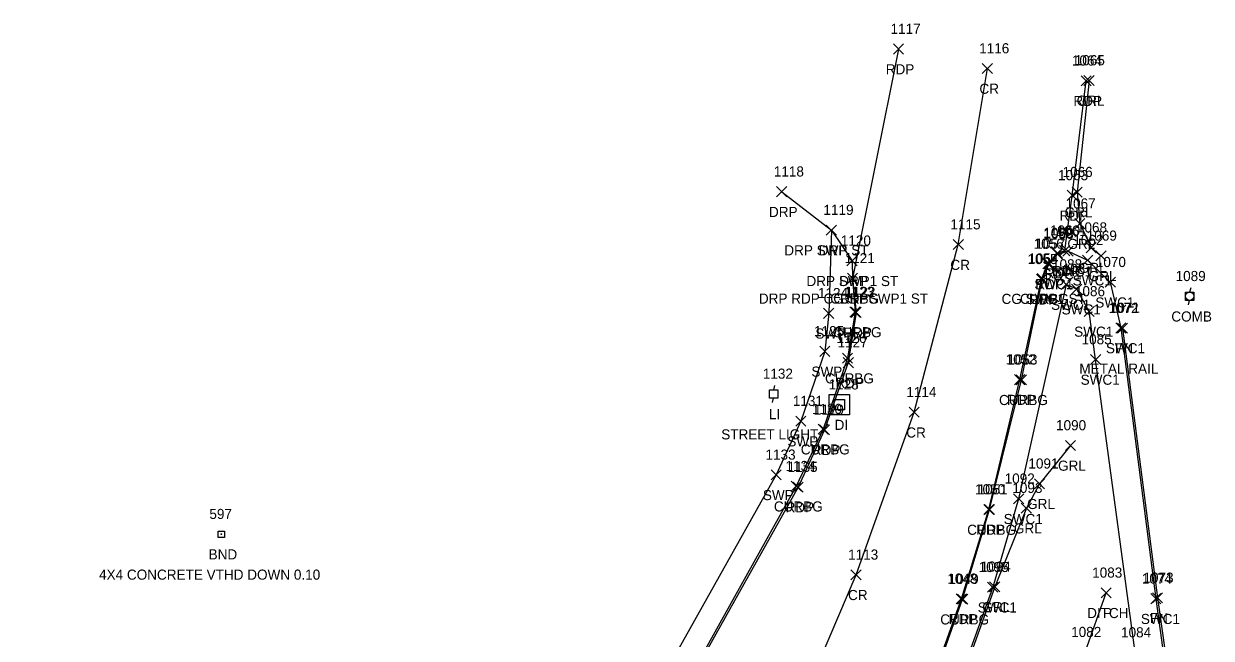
# Model space of a CAD drawing. Extents: x 1690689 to 1696275, y 438760 to 444007.
# Drawn here: x 1692953 to 1693187.6, y 438961.2 to 439082.7 of the extents above; entities that cross this region are included whole.
import ezdxf

# ---------------------------------------------------------------- set-up
doc = ezdxf.new("R2010")
doc.units = 0
for name, color, linetype in [('D_A', 7, 'Continuous'), ('D_I', 7, 'Continuous'), ('D_TIC', 7, 'Continuous'), ('DD', 7, 'Continuous'), ('DS', 7, 'Continuous'), ('L_A', 7, 'Continuous'), ('L_C', 7, 'Continuous'), ('L_I', 7, 'Continuous'), ('L_TIC', 7, 'Continuous'), ('Level 18', 7, 'Continuous'), ('LFNC', 7, 'Continuous'), ('M_A', 7, 'Continuous'), ('M_C', 7, 'Continuous'), ('M_I', 7, 'Continuous'), ('P_A', 7, 'Continuous'), ('P_I', 7, 'Continuous'), ('P_TIC', 7, 'Continuous'), ('PET', 7, 'Continuous'), ('PRC', 7, 'Continuous'), ('R_A', 7, 'Continuous'), ('R_I', 7, 'Continuous'), ('R_TIC', 7, 'Continuous'), ('RC', 7, 'Continuous'), ('RDP', 7, 'Continuous'), ('RGR', 7, 'Continuous'), ('RSW', 7, 'Continuous'), ('U_A', 7, 'Continuous'), ('U_C', 7, 'Continuous'), ('U_I', 7, 'Continuous'), ('ULP', 7, 'Continuous'), ('UP', 7, 'Continuous')]:
    doc.layers.add(name, color=color, linetype=linetype)

msp = doc.modelspace()

# ---------------------------------------------------------------- linework, layer by layer
at = {"layer": 'D_TIC'}
for points in [[(1693165.84, 438969.21), (1693167.84, 438971.21)], [(1693167.84, 438969.21), (1693165.84, 438971.21)], [(1693165.84, 438969.21), (1693167.84, 438971.21)], [(1693167.84, 438969.21), (1693165.84, 438971.21)]]:
    msp.add_lwpolyline(points, dxfattribs=at)
at = {"layer": 'DD'}
msp.add_lwpolyline([(1693142.76, 438898.51), (1693152.44, 438924.35), (1693162.69, 438958.47), (1693166.84, 438970.21)], dxfattribs=at)
at = {"layer": 'DS'}
for p, q in [((1693112.13, 439009.41), (1693116.13, 439009.41)), ((1693112.13, 439005.41), (1693112.13, 439009.41)), ((1693113.13, 439006.41), (1693113.13, 439008.41)), ((1693113.13, 439008.41), (1693115.13, 439008.41)), ((1693115.13, 439008.41), (1693115.13, 439006.41)), ((1693116.13, 439009.41), (1693116.13, 439005.41)), ((1693115.13, 439006.41), (1693113.13, 439006.41)), ((1693114.14, 439007.41), (1693114.14, 439007.41)), ((1693114.14, 439007.41), (1693114.14, 439007.41)), ((1693116.13, 439005.41), (1693112.13, 439005.41))]:
    msp.add_line(p, q, dxfattribs=at)
at = {"layer": 'L_TIC'}
for points in [[(1693169.07, 439021.53), (1693171.07, 439023.53)], [(1693171.07, 439021.53), (1693169.07, 439023.53)], [(1693175.98, 438968.21), (1693177.98, 438970.21)], [(1693177.98, 438968.21), (1693175.98, 438970.21)]]:
    msp.add_lwpolyline(points, dxfattribs=at)
at = {"layer": 'Level 18'}
msp.add_lwpolyline([(1692991.42, 438982.42), (1692992.67, 438982.42), (1692992.67, 438981.17), (1692991.42, 438981.17)], close=True, dxfattribs=at)
msp.add_circle((1692992.04, 438981.8), 0.0833, dxfattribs=at)
at = {"layer": 'LFNC'}
msp.add_lwpolyline([(1693170.07, 439022.53), (1693176.98, 438969.21), (1693182.65, 438929.09)], dxfattribs=at)
at = {"layer": 'P_TIC'}
for points in [[(1693124.8, 439076.7), (1693126.8, 439078.7)], [(1693126.8, 439076.7), (1693124.8, 439078.7)], [(1693142.37, 439072.85), (1693144.37, 439074.85)], [(1693144.37, 439072.85), (1693142.37, 439074.85)], [(1693161.88, 439070.43), (1693163.88, 439072.43)], [(1693163.88, 439070.43), (1693161.88, 439072.43)], [(1693159.14, 439047.77), (1693161.14, 439049.77)], [(1693161.14, 439047.77), (1693159.14, 439049.77)], [(1693136.63, 439038.04), (1693138.63, 439040.04)], [(1693138.63, 439038.04), (1693136.63, 439040.04)], [(1693157.65, 439036.84), (1693159.65, 439038.84)], [(1693159.65, 439036.84), (1693157.65, 439038.84)], [(1693156.21, 439036.36), (1693158.21, 439038.36)], [(1693158.21, 439036.36), (1693156.21, 439038.36)], [(1693154.34, 439034.22), (1693156.34, 439036.22)], [(1693156.34, 439034.22), (1693154.34, 439036.22)], [(1693115.74, 439031.37), (1693117.74, 439033.37)], [(1693117.74, 439031.37), (1693115.74, 439033.37)], [(1693153.07, 439031.19), (1693155.07, 439033.19)], [(1693155.07, 439031.19), (1693153.07, 439033.19)], [(1693116.43, 439024.65), (1693118.43, 439026.65)], [(1693118.43, 439024.65), (1693116.43, 439026.65)], [(1693114.9, 439014.71), (1693116.9, 439016.71)], [(1693116.9, 439014.71), (1693114.9, 439016.71)], [(1693148.76, 439011.35), (1693150.76, 439013.35)], [(1693150.76, 439011.35), (1693148.76, 439013.35)], [(1693127.92, 439004.9), (1693129.92, 439006.9)], [(1693129.92, 439004.9), (1693127.92, 439006.9)], [(1693110.21, 439001.42), (1693112.21, 439003.42)], [(1693112.21, 439001.42), (1693110.21, 439003.42)], [(1693105.01, 438990.1), (1693107.01, 438992.1)], [(1693107.01, 438990.1), (1693105.01, 438992.1)], [(1693142.65, 438985.67), (1693144.65, 438987.67)], [(1693144.65, 438985.67), (1693142.65, 438987.67)], [(1693116.42, 438972.77), (1693118.42, 438974.77)], [(1693118.42, 438972.77), (1693116.42, 438974.77)], [(1693137.23, 438968.02), (1693139.23, 438970.02)], [(1693139.23, 438968.02), (1693137.23, 438970.02)]]:
    msp.add_lwpolyline(points, dxfattribs=at)
at = {"layer": 'PET'}
for points in [[(1693125.8, 439077.7), (1693116.74, 439032.37), (1693117.43, 439025.65), (1693115.9, 439015.71), (1693111.21, 439002.42), (1693106.01, 438991.1), (1693085.1, 438953.79), (1693072.88, 438932.02), (1693062.34, 438914.66), (1693048.8, 438898.45), (1693044.46, 438895.45), (1693034.2, 438890.8), (1693027.9, 438888.88), (1693020.98, 438887.4), (1693013.55, 438887.23), (1693007.21, 438888.24), (1692984.73, 438894.57), (1692943.33, 438905.8), (1692898.33, 438918.08), (1692858.37, 438928.85), (1692835.39, 438935.21), (1692797.06, 438945.81)], [(1693178, 438831.35), (1693167.86, 438834.18), (1693150.55, 438839.03), (1693143.37, 438841.6), (1693136.29, 438844.87), (1693130.21, 438848.85), (1693123.67, 438855.48), (1693121.21, 438858.85), (1693116.99, 438868.32), (1693115.47, 438875.4), (1693115, 438883.12), (1693115.75, 438896.95), (1693117.89, 438910.42), (1693121.34, 438921.38), (1693129.29, 438944.07), (1693138.23, 438969.02), (1693143.65, 438986.67), (1693149.76, 439012.35), (1693154.07, 439032.19), (1693155.34, 439035.22), (1693157.21, 439037.36), (1693158.65, 439037.84), (1693160.14, 439048.77), (1693162.88, 439071.43)]]:
    msp.add_lwpolyline(points, dxfattribs=at)
at = {"layer": 'PRC'}
msp.add_lwpolyline([(1693075.4, 438881.17), (1693089.6, 438911.3), (1693103.78, 438941.64), (1693117.42, 438973.77), (1693128.92, 439005.9), (1693137.63, 439039.04), (1693143.37, 439073.85)], dxfattribs=at)
at = {"layer": 'R_TIC'}
for points in [[(1693162.45, 439070.49), (1693164.45, 439072.49)], [(1693164.45, 439070.49), (1693162.45, 439072.49)], [(1693101.74, 439048.5), (1693103.74, 439050.5)], [(1693103.74, 439048.5), (1693101.74, 439050.5)], [(1693160.09, 439048.4), (1693162.09, 439050.4)], [(1693162.09, 439048.4), (1693160.09, 439050.4)], [(1693160.63, 439042.18), (1693162.63, 439044.18)], [(1693162.63, 439042.18), (1693160.63, 439044.18)], [(1693111.55, 439040.91), (1693113.55, 439042.91)], [(1693113.55, 439040.91), (1693111.55, 439042.91)], [(1693111.55, 439040.91), (1693113.55, 439042.91)], [(1693113.55, 439040.91), (1693111.55, 439042.91)], [(1693158.3, 439036.74), (1693160.3, 439038.74)], [(1693160.3, 439036.74), (1693158.3, 439038.74)], [(1693162.88, 439037.44), (1693164.88, 439039.44)], [(1693164.88, 439037.44), (1693162.88, 439039.44)], [(1693115.63, 439034.84), (1693117.63, 439036.84)], [(1693117.63, 439034.84), (1693115.63, 439036.84)], [(1693115.63, 439034.84), (1693117.63, 439036.84)], [(1693117.63, 439034.84), (1693115.63, 439036.84)], [(1693154.6, 439034.22), (1693156.6, 439036.22)], [(1693156.6, 439034.22), (1693154.6, 439036.22)], [(1693156.23, 439036.18), (1693158.23, 439038.18)], [(1693158.23, 439036.18), (1693156.23, 439038.18)], [(1693162.18, 439034.96), (1693164.18, 439036.96)], [(1693164.18, 439034.96), (1693162.18, 439036.96)], [(1693164.82, 439035.82), (1693166.82, 439037.82)], [(1693166.82, 439035.82), (1693164.82, 439037.82)], [(1693115.74, 439031.37), (1693117.74, 439033.37)], [(1693117.74, 439031.37), (1693115.74, 439033.37)], [(1693115.74, 439031.37), (1693117.74, 439033.37)], [(1693117.74, 439031.37), (1693115.74, 439033.37)], [(1693115.74, 439031.37), (1693117.74, 439033.37)], [(1693117.74, 439031.37), (1693115.74, 439033.37)], [(1693153.23, 439031.31), (1693155.23, 439033.31)], [(1693155.23, 439031.31), (1693153.23, 439033.31)], [(1693153.23, 439031.31), (1693155.23, 439033.31)], [(1693155.23, 439031.31), (1693153.23, 439033.31)], [(1693157.92, 439030.14), (1693159.92, 439032.14)], [(1693159.92, 439030.14), (1693157.92, 439032.14)], [(1693166.65, 439030.6), (1693168.65, 439032.6)], [(1693168.65, 439030.6), (1693166.65, 439032.6)], [(1693160.01, 439029.23), (1693162.01, 439031.23)], [(1693162.01, 439029.23), (1693160.01, 439031.23)], [(1693111.03, 439024.46), (1693113.03, 439026.46)], [(1693113.03, 439024.46), (1693111.03, 439026.46)], [(1693116.22, 439024.72), (1693118.22, 439026.72)], [(1693118.22, 439024.72), (1693116.22, 439026.72)], [(1693162.48, 439024.83), (1693164.48, 439026.83)], [(1693164.48, 439024.83), (1693162.48, 439026.83)], [(1693168.75, 439021.56), (1693170.75, 439023.56)], [(1693170.75, 439021.56), (1693168.75, 439023.56)], [(1693110.25, 439016.93), (1693112.25, 439018.93)], [(1693112.25, 439016.93), (1693110.25, 439018.93)], [(1693114.72, 439015.6), (1693116.72, 439017.6)], [(1693116.72, 439015.6), (1693114.72, 439017.6)], [(1693163.75, 439015.33), (1693165.75, 439017.33)], [(1693165.75, 439015.33), (1693163.75, 439017.33)], [(1693149.08, 439011.32), (1693151.08, 439013.32)], [(1693151.08, 439011.32), (1693149.08, 439013.32)], [(1693105.5, 439003.15), (1693107.5, 439005.15)], [(1693107.5, 439003.15), (1693105.5, 439005.15)], [(1693109.92, 439001.56), (1693111.92, 439003.56)], [(1693111.92, 439001.56), (1693109.92, 439003.56)], [(1693158.79, 438998.34), (1693160.79, 439000.34)], [(1693160.79, 438998.34), (1693158.79, 439000.34)], [(1693100.66, 438992.53), (1693102.66, 438994.53)], [(1693102.66, 438992.53), (1693100.66, 438994.53)], [(1693104.62, 438990.28), (1693106.62, 438992.28)], [(1693106.62, 438990.28), (1693104.62, 438992.28)], [(1693152.67, 438990.77), (1693154.67, 438992.77)], [(1693154.67, 438990.77), (1693152.67, 438992.77)], [(1693148.55, 438987.8), (1693150.55, 438989.8)], [(1693150.55, 438987.8), (1693148.55, 438989.8)], [(1693142.79, 438985.67), (1693144.79, 438987.67)], [(1693144.79, 438985.67), (1693142.79, 438987.67)], [(1693150.07, 438985.95), (1693152.07, 438987.95)], [(1693152.07, 438985.95), (1693150.07, 438987.95)], [(1693143.42, 438970.31), (1693145.42, 438972.31)], [(1693145.42, 438970.31), (1693143.42, 438972.31)], [(1693143.82, 438970.39), (1693145.82, 438972.39)], [(1693145.82, 438970.39), (1693143.82, 438972.39)], [(1693137.48, 438967.95), (1693139.48, 438969.95)], [(1693139.48, 438967.95), (1693137.48, 438969.95)], [(1693175.65, 438968.04), (1693177.65, 438970.04)], [(1693177.65, 438968.04), (1693175.65, 438970.04)]]:
    msp.add_lwpolyline(points, dxfattribs=at)
at = {"layer": 'RC'}
for points in [[(1693116.74, 439032.37), (1693117.22, 439025.72), (1693115.72, 439016.6), (1693110.92, 439002.56), (1693105.62, 438991.28), (1693084.72, 438953.77), (1693072.69, 438932.15), (1693062.14, 438914.84), (1693048.64, 438898.6), (1693044.15, 438895.89), (1693034.18, 438890.95), (1693027.86, 438888.9)], [(1693178.03, 438831.53), (1693167.9, 438834.34), (1693150.57, 438839.37), (1693143.21, 438842), (1693136.42, 438845.08), (1693130.37, 438849.2), (1693123.91, 438855.55), (1693121.54, 438858.8), (1693117.19, 438868.37), (1693115.74, 438875.3), (1693115.29, 438883.15), (1693116, 438896.82), (1693118.16, 438910.25), (1693121.66, 438921.37), (1693129.62, 438944.14), (1693138.48, 438968.95), (1693143.79, 438986.67), (1693150.08, 439012.32), (1693154.23, 439032.31)]]:
    msp.add_lwpolyline(points, dxfattribs=at)
at = {"layer": 'RDP'}
msp.add_lwpolyline([(1693102.74, 439049.5), (1693112.55, 439041.91), (1693116.63, 439035.84), (1693116.74, 439032.37)], dxfattribs=at)
at = {"layer": 'RGR'}
for points in [[(1693163.45, 439071.49), (1693161.09, 439049.4), (1693161.63, 439043.18), (1693163.88, 439038.44), (1693165.82, 439036.82)], [(1693159.79, 438999.34), (1693153.67, 438991.77), (1693151.07, 438986.95), (1693144.82, 438971.39), (1693131.24, 438933.34), (1693124.53, 438914.58), (1693122.5, 438903.99), (1693122.82, 438892.2), (1693126.09, 438880.92), (1693132.92, 438869.11)]]:
    msp.add_lwpolyline(points, dxfattribs=at)
at = {"layer": 'RSW'}
for points in [[(1693112.55, 439041.91), (1693112.03, 439025.46), (1693111.25, 439017.93), (1693106.5, 439004.15), (1693101.66, 438993.53), (1693080.63, 438956.05), (1693068.27, 438934.74), (1693058, 438916.81), (1693045.81, 438902.02), (1693041.81, 438899.51), (1693032.24, 438894.76), (1693028.09, 438893.51), (1693028.9, 438889.85)], [(1693154.23, 439032.31), (1693155.6, 439035.22), (1693157.23, 439037.18), (1693159.3, 439037.74), (1693163.18, 439035.96), (1693167.65, 439031.6), (1693169.75, 439022.56), (1693176.65, 438969.04), (1693182.18, 438928.53)], [(1693177.08, 438924.94), (1693172.55, 438958.4), (1693164.75, 439016.33), (1693163.48, 439025.83), (1693161.01, 439030.23), (1693158.92, 439031.14), (1693149.55, 438988.8), (1693144.42, 438971.31), (1693130.82, 438933.51), (1693124.32, 438914.54), (1693122.2, 438903.76), (1693122.52, 438892.17), (1693125.86, 438880.79), (1693130.11, 438872.39)]]:
    msp.add_lwpolyline(points, dxfattribs=at)
at = {"layer": 'ULP'}
for p, q in [((1693101.31, 439011.19), (1693101.14, 439010.36)), ((1693100.31, 439008.69), (1693100.31, 439010.36)), ((1693100.31, 439010.36), (1693101.97, 439010.36)), ((1693101.97, 439008.69), (1693100.31, 439008.69)), ((1693100.89, 439007.86), (1693101.14, 439008.69)), ((1693101.14, 439009.53), (1693101.14, 439009.53)), ((1693101.97, 439010.36), (1693101.97, 439008.69))]:
    msp.add_line(p, q, dxfattribs=at)
at = {"layer": 'UP'}
for p, q in [((1693182.49, 439027.99), (1693182.49, 439029.66)), ((1693182.49, 439029.66), (1693184.16, 439029.66)), ((1693183.58, 439030.49), (1693183.33, 439029.66)), ((1693184.16, 439029.66), (1693184.16, 439027.99)), ((1693184.16, 439027.99), (1693182.49, 439027.99)), ((1693183.08, 439027.16), (1693183.33, 439027.99)), ((1693183.33, 439028.83), (1693183.33, 439028.83))]:
    msp.add_line(p, q, dxfattribs=at)
msp.add_circle((1693183.33, 439028.83), 0.833, dxfattribs=at)

# ---------------------------------------------------------------- texts
at = {"layer": 'D_A'}
for s, p in [('DI', (1693113.19, 439002.41)), ('DITCH', (1693163.08, 438965.21)), ('P', (1693166.22, 438965.21))]:
    msp.add_text(s, height=2, dxfattribs=at).set_placement(p)
at = {"layer": 'D_I'}
for s, p in [('1128', (1693112.01, 439010.41)), ('1083', (1693164.07, 438973.21)), ('1083', (1693164.07, 438973.21)), ('1082', (1693159.92, 438961.47))]:
    msp.add_text(s, height=2, dxfattribs=at).set_placement(p)
at = {"layer": 'L_A'}
for p in [(1693168.56, 439017.53), (1693175.46, 438964.21)]:
    msp.add_text('FN', height=2, dxfattribs=at).set_placement(p)
at = {"layer": 'L_C'}
msp.add_text('METAL RAIL', height=2, dxfattribs=at).set_placement((1693161.54, 439013.53))
at = {"layer": 'L_I'}
for s, p in [('1072', (1693167.3, 439025.53)), ('1073', (1693174.2, 438972.21))]:
    msp.add_text(s, height=2, dxfattribs=at).set_placement(p)
at = {"layer": 'M_A'}
msp.add_text('BND', height=2, dxfattribs=at).set_placement((1692989.53, 438976.8))
at = {"layer": 'M_C'}
msp.add_text('4X4 CONCRETE VTHD DOWN 0.10', height=2, dxfattribs=at).set_placement((1692967.89, 438972.8))
at = {"layer": 'M_I'}
msp.add_text('597', height=2, dxfattribs=at).set_placement((1692989.68, 438984.8))
at = {"layer": 'P_A'}
for s, p in [('RDP', (1693123.29, 439072.7)), ('CR', (1693141.8, 439068.85)), ('RDP', (1693160.37, 439066.43)), ('RDP', (1693157.62, 439043.77)), ('CR', (1693136.06, 439034.04)), ('RDP', (1693154.7, 439032.36)), ('RDP', (1693156.14, 439032.84)), ('RDP', (1693152.83, 439030.22)), ('RDP', (1693114.23, 439027.37)), ('RDP', (1693151.55, 439027.19)), ('RDP', (1693114.91, 439020.65)), ('RDP', (1693113.39, 439010.71)), ('RDP', (1693147.24, 439007.35)), ('CR', (1693127.35, 439000.9)), ('RDP', (1693108.7, 438997.42)), ('RDP', (1693103.5, 438986.1)), ('RDP', (1693141.14, 438981.67)), ('CR', (1693115.85, 438968.77)), ('RDP', (1693135.72, 438964.02))]:
    msp.add_text(s, height=2, dxfattribs=at).set_placement(p)
at = {"layer": 'P_I'}
for s, p in [('1117', (1693124.24, 439080.7)), ('1116', (1693141.75, 439076.85)), ('1064', (1693160.06, 439074.43)), ('1063', (1693157.32, 439051.77)), ('1115', (1693136.07, 439042.04)), ('1059', (1693154.43, 439040.36)), ('1060', (1693155.74, 439040.84)), ('1056', (1693152.51, 439038.22)), ('1121', (1693115.18, 439035.37)), ('1055', (1693151.29, 439035.19)), ('1122', (1693115.3, 439028.65)), ('1127', (1693113.78, 439018.71)), ('1052', (1693146.98, 439015.35)), ('1114', (1693127.36, 439008.9)), ('1129', (1693109.08, 439005.42)), ('1135', (1693103.89, 438994.1)), ('1051', (1693141.44, 438989.67)), ('1113', (1693115.86, 438976.77)), ('1048', (1693135.46, 438972.02))]:
    msp.add_text(s, height=2, dxfattribs=at).set_placement(p)
at = {"layer": 'R_A'}
for s, p in [('GRL', (1693161, 439066.49)), ('DRP', (1693100.23, 439044.5)), ('GRL', (1693158.64, 439044.4)), ('DRP SWP ST', (1693103.26, 439036.91)), ('DRP', (1693110.03, 439036.91)), ('GRL', (1693159.18, 439038.18)), ('SWC1', (1693154.27, 439032.18)), ('SWC1', (1693156.34, 439032.74)), ('GRL', (1693161.42, 439033.44)), ('DRP SWP1 ST', (1693107.63, 439030.84)), ('DRP', (1693114.12, 439030.84)), ('SWC1', (1693152.64, 439030.22)), ('SWC1', (1693160.22, 439030.96)), ('GRL', (1693163.37, 439031.82)), ('DRP RDP CG ST SWP1 ST', (1693098.23, 439027.37)), ('CURBG', (1693112.33, 439027.37)), ('DRP', (1693114.23, 439027.37)), ('CG SWC1 ST', (1693146.17, 439027.31)), ('CURBG', (1693149.81, 439027.31)), ('SWC1', (1693155.95, 439026.14)), ('SWC1', (1693158.05, 439025.23)), ('SWC1', (1693164.69, 439026.6)), ('SWP', (1693109.39, 439020.46)), ('CURBG', (1693112.8, 439020.72)), ('SWC1', (1693160.52, 439020.83)), ('SWC1', (1693166.79, 439017.56)), ('SWP', (1693108.61, 439012.93)), ('CURBG', (1693111.3, 439011.6)), ('SWC1', (1693161.79, 439011.33)), ('CURBG', (1693145.67, 439007.32)), ('SWP', (1693103.86, 438999.15)), ('CURBG', (1693106.51, 438997.56)), ('GRL', (1693157.33, 438994.34)), ('SWP', (1693099.02, 438988.53)), ('CURBG', (1693101.2, 438986.28)), ('GRL', (1693151.22, 438986.77)), ('SWC1', (1693146.59, 438983.8)), ('CURBG', (1693139.38, 438981.67)), ('GRL', (1693148.61, 438981.95)), ('SWC1', (1693141.46, 438966.31)), ('GRL', (1693142.37, 438966.39)), ('CURBG', (1693134.06, 438963.95)), ('SWC1', (1693173.69, 438964.04))]:
    msp.add_text(s, height=2, dxfattribs=at).set_placement(p)
at = {"layer": 'R_I'}
for s, p in [('1065', (1693160.63, 439074.49)), ('1118', (1693101.18, 439052.5)), ('1066', (1693158.22, 439052.4)), ('1067', (1693158.81, 439046.18)), ('1119', (1693110.98, 439044.91)), ('1119', (1693110.98, 439044.91)), ('1068', (1693161.06, 439041.44)), ('1058', (1693154.46, 439040.18)), ('1061', (1693157.05, 439040.74)), ('1062', (1693160.36, 439038.96)), ('1069', (1693163, 439039.82)), ('1120', (1693114.42, 439038.84)), ('1120', (1693114.42, 439038.84)), ('1057', (1693152.83, 439038.22)), ('1121', (1693115.18, 439035.37)), ('1121', (1693115.18, 439035.37)), ('1121', (1693115.18, 439035.37)), ('1054', (1693151.46, 439035.31)), ('1054', (1693151.46, 439035.31)), ('1070', (1693164.79, 439034.6)), ('1088', (1693156.14, 439034.14)), ('1087', (1693158.24, 439033.23)), ('1124', (1693109.9, 439028.46)), ('1123', (1693115.09, 439028.72)), ('1086', (1693160.66, 439028.83)), ('1071', (1693167.54, 439025.56)), ('1125', (1693109.12, 439020.93)), ('1126', (1693113.54, 439019.6)), ('1085', (1693161.98, 439019.33)), ('1053', (1693147.31, 439015.32)), ('1131', (1693104.94, 439007.15)), ('1130', (1693108.71, 439005.56)), ('1090', (1693156.93, 439002.34)), ('1133', (1693099.54, 438996.53)), ('1091', (1693151.47, 438994.77)), ('1134', (1693103.49, 438994.28)), ('1050', (1693140.93, 438989.67)), ('1092', (1693146.78, 438991.8)), ('1093', (1693148.3, 438989.95)), ('1095', (1693141.65, 438974.31)), ('1094', (1693142.05, 438974.39)), ('1049', (1693135.7, 438971.95)), ('1074', (1693173.88, 438972.04)), ('1084', (1693169.78, 438961.4))]:
    msp.add_text(s, height=2, dxfattribs=at).set_placement(p)
at = {"layer": 'U_A'}
for s, p in [('COMB', (1693179.71, 439023.83)), ('LI', (1693100.24, 439004.53))]:
    msp.add_text(s, height=2, dxfattribs=at).set_placement(p)
at = {"layer": 'U_C'}
msp.add_text('STREET LIGHT', height=2, dxfattribs=at).set_placement((1693090.8, 439000.53))
at = {"layer": 'U_I'}
for s, p in [('1089', (1693180.55, 439031.83)), ('1132', (1693099.01, 439012.53))]:
    msp.add_text(s, height=2, dxfattribs=at).set_placement(p)

doc.saveas('drawing.dxf')
